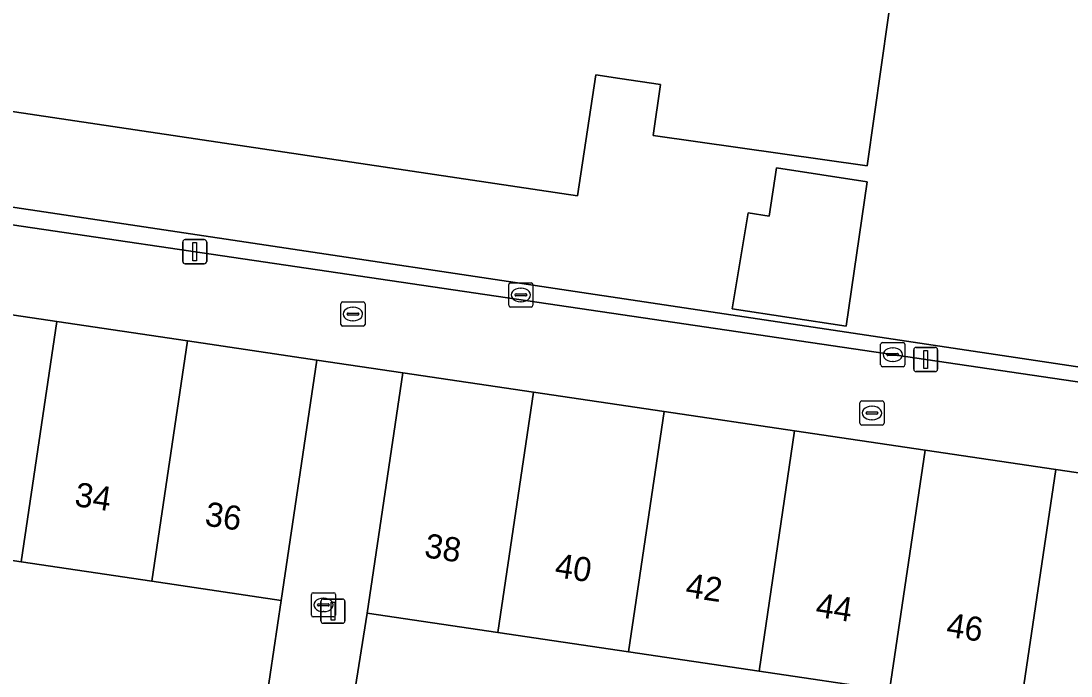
# Model space of a CAD drawing. Extents: x 164148 to 165261, y 382513 to 383432.
# Drawn here: x 164475.24 to 164518.66, y 383338.67 to 383365.77 of the extents above; entities that cross this region are included whole.
import ezdxf

# ---------------------------------------------------------------- set-up
doc = ezdxf.new("R2010")
doc.units = 0
for name, color, linetype in [('IMGEO_Brandkraan', 7, 'Continuous'), ('IMGEO_Erf', 7, 'Continuous'), ('IMGEO_Groenvoorziening', 7, 'Continuous'), ('IMGEO_Hek', 7, 'Continuous'), ('IMGEO_Kolk', 7, 'Continuous'), ('IMGEO_Lichtmast', 7, 'Continuous'), ('IMGEO_Pand', 7, 'Continuous'), ('IMGEO_Pand_nummerreeks', 7, 'Continuous'), ('IMGEO_Rioolput', 7, 'Continuous'), ('IMGEO_Voetpad_open', 7, 'Continuous')]:
    doc.layers.add(name, color=color, linetype=linetype)

msp = doc.modelspace()

# ---------------------------------------------------------------- linework, layer by layer
at = {"layer": 'IMGEO_Brandkraan'}
for p, q in [((164509.93, 383349.123), (164509.93, 383349.975)), ((164510.005, 383350.049), (164510.857, 383350.049)), ((164510.418, 383349.829), (164510.443, 383349.829)), ((164510.931, 383349.975), (164510.931, 383349.123)), ((164510.189, 383349.543), (164510.189, 383349.555)), ((164510.627, 383349.506), (164510.229, 383349.506)), ((164510.232, 383349.592), (164510.63, 383349.592)), ((164510.673, 383349.555), (164510.673, 383349.543)), ((164510.857, 383349.049), (164510.005, 383349.049)), ((164510.441, 383349.269), (164510.416, 383349.269))]:
    msp.add_line(p, q, dxfattribs=at)
for points in [[(164509.93, 383349.123), (164509.93, 383349.975)], [(164510.005, 383350.049), (164510.857, 383350.049)], [(164510.931, 383349.975), (164510.931, 383349.123)], [(164510.857, 383349.049), (164510.005, 383349.049)]]:
    msp.add_lwpolyline(points, dxfattribs=at)
for centre, radius, start, end in [((164510.007, 383349.973), 0.0765, 91.552, 178.448), ((164510.007, 383349.973), 0.0765, 91.552, 178.448), ((164510.855, 383349.973), 0.0765, 1.552, 88.448), ((164510.855, 383349.973), 0.0765, 1.552, 88.448), ((164510.229, 383349.552), 0.0403, 85.8775, 175.7526), ((164510.226, 383349.542), 0.0366, 178.938, 274.7102), ((164510.63, 383349.549), 0.043, 264.8664, 352.4533), ((164510.634, 383349.554), 0.0386, 1.7309, 96.639), ((164510.007, 383349.125), 0.0765, 181.552, 268.448), ((164510.007, 383349.125), 0.0765, 181.552, 268.448), ((164510.855, 383349.125), 0.0765, 271.552, 358.448), ((164510.855, 383349.125), 0.0765, 271.552, 358.448)]:
    msp.add_arc(centre, radius, start, end, dxfattribs=at)
for centre, major_axis, ratio, start_param, end_param in [((164510.417, 383349.549), (-0.387, 0.002), 0.722429, 4.712389, 7.853982), ((164510.442, 383349.549), (-0.39, 0.002), 0.717154, 1.570796, 4.712389)]:
    msp.add_ellipse(centre, major_axis=major_axis, ratio=ratio, start_param=start_param, end_param=end_param, dxfattribs=at)
at = {"layer": 'IMGEO_Erf'}
for points in [[(164496.172, 383394.152), (164495.205, 383395.312), (164485.846, 383406.541), (164475.669, 383398.705), (164457.962, 383391.157), (164451.983, 383388.33), (164443.993, 383384.279), (164439.097, 383382.204), (164431.513, 383378.99), (164421.044, 383374.785), (164425.292, 383365.326), (164446.405, 383362.194), (164456.026, 383360.895), (164526.656, 383350.3), (164530.567, 383353.579)], [(164506.481, 383359.697), (164510.237, 383359.121), (164509.366, 383353.137), (164504.653, 383353.864), (164505.307, 383357.838), (164506.183, 383357.694)], [(164480.652, 383342.588), (164475.251, 383343.388), (164469.85, 383344.188), (164464.449, 383344.988), (164459.047, 383345.788), (164453.646, 383346.588), (164448.245, 383347.387), (164442.844, 383348.187), (164437.443, 383348.987), (164432.042, 383349.787), (164430.539, 383340.579), (164484.639, 383332.608), (164486.005, 383341.796)], [(164527.364, 383335.671), (164521.963, 383336.471), (164516.562, 383337.27), (164511.161, 383338.07), (164505.76, 383338.87), (164500.359, 383339.67), (164494.958, 383340.47), (164489.556, 383341.27), (164488.094, 383332.078), (164531.533, 383325.667), (164532.785, 383334.868)]]:
    msp.add_lwpolyline(points, close=True, dxfattribs=at)
msp.add_lwpolyline([(164511.684, 383370.001), (164510.233, 383359.776), (164501.382, 383361.033), (164501.681, 383363.14), (164500, 383363.392), (164499.006, 383363.541), (164498.259, 383358.532), (164472.187, 383362.422), (164472.098, 383361.829), (164466.687, 383362.633), (164467.658, 383369.162)], dxfattribs=at)
at = {"layer": 'IMGEO_Groenvoorziening'}
msp.add_lwpolyline([(164433.986, 383363.368), (164526.587, 383349.71), (164526.656, 383350.3), (164456.026, 383360.895), (164446.405, 383362.194), (164425.292, 383365.326), (164425.46, 383364.655)], close=True, dxfattribs=at)
at = {"layer": 'IMGEO_Hek'}
msp.add_lwpolyline([(164526.656, 383350.3), (164456.026, 383360.895), (164446.405, 383362.194), (164425.292, 383365.326)], dxfattribs=at)
at = {"layer": 'IMGEO_Kolk'}
for p, q in [((164495.409, 383354.01), (164495.409, 383354.862)), ((164495.484, 383354.936), (164496.336, 383354.936)), ((164495.897, 383354.716), (164495.922, 383354.716)), ((164496.41, 383354.862), (164496.41, 383354.01)), ((164495.668, 383354.43), (164495.668, 383354.442)), ((164496.106, 383354.393), (164495.708, 383354.393)), ((164495.711, 383354.479), (164496.109, 383354.479)), ((164495.92, 383354.156), (164495.895, 383354.156)), ((164496.152, 383354.442), (164496.152, 383354.43)), ((164496.336, 383353.936), (164495.484, 383353.936)), ((164510.864, 383352.467), (164511.716, 383352.467)), ((164510.789, 383351.541), (164510.789, 383352.393)), ((164511.091, 383352.01), (164511.489, 383352.01)), ((164511.277, 383352.247), (164511.302, 383352.247)), ((164511.79, 383352.393), (164511.79, 383351.541)), ((164511.048, 383351.961), (164511.048, 383351.973)), ((164511.486, 383351.924), (164511.088, 383351.924)), ((164511.3, 383351.687), (164511.275, 383351.687)), ((164511.532, 383351.973), (164511.532, 383351.961)), ((164511.716, 383351.467), (164510.864, 383351.467)), ((164487.247, 383341.185), (164487.247, 383342.037)), ((164487.322, 383342.111), (164488.174, 383342.111)), ((164488.248, 383342.037), (164488.248, 383341.185)), ((164487.506, 383341.605), (164487.506, 383341.617)), ((164487.944, 383341.568), (164487.546, 383341.568)), ((164487.549, 383341.654), (164487.947, 383341.654)), ((164487.735, 383341.891), (164487.76, 383341.891)), ((164487.99, 383341.617), (164487.99, 383341.605)), ((164487.758, 383341.331), (164487.733, 383341.331)), ((164488.174, 383341.111), (164487.322, 383341.111))]:
    msp.add_line(p, q, dxfattribs=at)
for points in [[(164495.409, 383354.01), (164495.409, 383354.862)], [(164495.484, 383354.936), (164496.336, 383354.936)], [(164496.41, 383354.862), (164496.41, 383354.01)], [(164496.336, 383353.936), (164495.484, 383353.936)], [(164510.864, 383352.467), (164511.716, 383352.467)], [(164510.789, 383351.541), (164510.789, 383352.393)], [(164511.79, 383352.393), (164511.79, 383351.541)], [(164511.716, 383351.467), (164510.864, 383351.467)], [(164487.247, 383341.185), (164487.247, 383342.037)], [(164487.322, 383342.111), (164488.174, 383342.111)], [(164488.248, 383342.037), (164488.248, 383341.185)], [(164488.174, 383341.111), (164487.322, 383341.111)]]:
    msp.add_lwpolyline(points, dxfattribs=at)
for centre, radius, start, end in [((164495.486, 383354.86), 0.0765, 91.552, 178.448), ((164495.486, 383354.86), 0.0765, 91.552, 178.448), ((164496.334, 383354.86), 0.0765, 1.552, 88.448), ((164496.334, 383354.86), 0.0765, 1.552, 88.448), ((164495.708, 383354.439), 0.0403, 85.8775, 175.7526), ((164495.705, 383354.429), 0.0366, 178.938, 274.7102), ((164496.109, 383354.436), 0.043, 264.8664, 352.4533), ((164496.113, 383354.441), 0.0386, 1.7309, 96.639), ((164495.486, 383354.012), 0.0765, 181.552, 268.448), ((164495.486, 383354.012), 0.0765, 181.552, 268.448), ((164496.334, 383354.012), 0.0765, 271.552, 358.448), ((164496.334, 383354.012), 0.0765, 271.552, 358.448), ((164510.866, 383352.391), 0.0765, 91.552, 178.448), ((164510.866, 383352.391), 0.0765, 91.552, 178.448), ((164511.714, 383352.391), 0.0765, 1.552, 88.448), ((164511.714, 383352.391), 0.0765, 1.552, 88.448), ((164511.088, 383351.97), 0.0403, 85.8775, 175.7526), ((164511.493, 383351.972), 0.0386, 1.7309, 96.639), ((164511.085, 383351.96), 0.0366, 178.938, 274.7102), ((164511.489, 383351.967), 0.043, 264.8664, 352.4533), ((164510.866, 383351.543), 0.0765, 181.552, 268.448), ((164510.866, 383351.543), 0.0765, 181.552, 268.448), ((164511.714, 383351.543), 0.0765, 271.552, 358.448), ((164511.714, 383351.543), 0.0765, 271.552, 358.448), ((164487.324, 383342.035), 0.0765, 91.552, 178.448), ((164487.324, 383342.035), 0.0765, 91.552, 178.448), ((164488.172, 383342.035), 0.0765, 1.552, 88.448), ((164488.172, 383342.035), 0.0765, 1.552, 88.448), ((164487.546, 383341.614), 0.0403, 85.8775, 175.7526), ((164487.543, 383341.604), 0.0366, 178.938, 274.7102), ((164487.947, 383341.611), 0.043, 264.8664, 352.4533), ((164487.951, 383341.616), 0.0386, 1.7309, 96.639), ((164487.324, 383341.187), 0.0765, 181.552, 268.448), ((164487.324, 383341.187), 0.0765, 181.552, 268.448), ((164488.172, 383341.187), 0.0765, 271.552, 358.448), ((164488.172, 383341.187), 0.0765, 271.552, 358.448)]:
    msp.add_arc(centre, radius, start, end, dxfattribs=at)
for centre, major_axis, ratio, start_param, end_param in [((164495.896, 383354.436), (-0.387, 0.002), 0.722429, 4.712389, 7.853982), ((164495.921, 383354.436), (-0.39, 0.002), 0.717154, 1.570796, 4.712389), ((164511.276, 383351.967), (-0.387, 0.002), 0.722429, 4.712389, 7.853982), ((164511.301, 383351.967), (-0.39, 0.002), 0.717154, 1.570796, 4.712389), ((164487.734, 383341.611), (-0.387, 0.002), 0.722429, 4.712389, 7.853982), ((164487.759, 383341.611), (-0.39, 0.002), 0.717154, 1.570796, 4.712389)]:
    msp.add_ellipse(centre, major_axis=major_axis, ratio=ratio, start_param=start_param, end_param=end_param, dxfattribs=at)
at = {"layer": 'IMGEO_Lichtmast'}
for p, q in [((164481.928, 383355.824), (164481.928, 383356.624)), ((164481.928, 383356.624), (164481.928, 383355.824)), ((164482.028, 383356.724), (164482.818, 383356.724)), ((164482.818, 383356.724), (164482.028, 383356.724)), ((164482.918, 383356.624), (164482.918, 383355.824)), ((164482.918, 383355.824), (164482.918, 383356.624)), ((164482.818, 383355.724), (164482.028, 383355.724)), ((164482.028, 383355.724), (164482.818, 383355.724)), ((164512.155, 383351.366), (164512.155, 383352.166)), ((164512.155, 383352.166), (164512.155, 383351.366)), ((164512.255, 383352.266), (164513.045, 383352.266)), ((164513.045, 383352.266), (164512.255, 383352.266)), ((164513.145, 383352.166), (164513.145, 383351.366)), ((164513.145, 383351.366), (164513.145, 383352.166)), ((164513.045, 383351.266), (164512.255, 383351.266)), ((164512.255, 383351.266), (164513.045, 383351.266)), ((164487.643, 383340.949), (164487.643, 383341.749)), ((164487.643, 383341.749), (164487.643, 383340.949)), ((164487.743, 383341.849), (164488.533, 383341.849)), ((164488.533, 383341.849), (164487.743, 383341.849)), ((164488.633, 383341.749), (164488.633, 383340.949)), ((164488.633, 383340.949), (164488.633, 383341.749)), ((164488.533, 383340.849), (164487.743, 383340.849)), ((164487.743, 383340.849), (164488.533, 383340.849))]:
    msp.add_line(p, q, dxfattribs=at)
for points in [[(164482.348, 383356.599), (164482.498, 383356.599), (164482.498, 383355.849), (164482.348, 383355.849), (164482.348, 383356.599)], [(164512.575, 383352.141), (164512.725, 383352.141), (164512.725, 383351.391), (164512.575, 383351.391), (164512.575, 383352.141)], [(164488.063, 383341.724), (164488.213, 383341.724), (164488.213, 383340.974), (164488.063, 383340.974), (164488.063, 383341.724)]]:
    msp.add_lwpolyline(points, dxfattribs=at)
for centre, start, end in [((164482.028, 383356.624), 90, 180), ((164482.028, 383356.624), 90, 180), ((164482.818, 383356.624), 0, 90), ((164482.818, 383356.624), 360, 90), ((164482.028, 383355.824), 180, 270), ((164482.028, 383355.824), 180, 270), ((164482.818, 383355.824), 270, 0), ((164482.818, 383355.824), 270, 0), ((164512.255, 383352.166), 90, 180), ((164512.255, 383352.166), 90, 180), ((164513.045, 383352.166), 0, 90), ((164513.045, 383352.166), 360, 90), ((164512.255, 383351.366), 180, 270), ((164512.255, 383351.366), 180, 270), ((164513.045, 383351.366), 270, 0), ((164513.045, 383351.366), 270, 0), ((164487.743, 383341.749), 90, 180), ((164487.743, 383341.749), 90, 180), ((164488.533, 383341.749), 0, 90), ((164488.533, 383341.749), 360, 90), ((164487.743, 383340.949), 180, 270), ((164487.743, 383340.949), 180, 270), ((164488.533, 383340.949), 270, 0), ((164488.533, 383340.949), 270, 0)]:
    msp.add_arc(centre, 0.1, start, end, dxfattribs=at)
at = {"layer": 'IMGEO_Pand'}
msp.add_lwpolyline([(164467.658, 383369.162), (164466.687, 383362.633), (164472.098, 383361.829), (164472.187, 383362.422), (164498.259, 383358.532), (164499.006, 383363.541), (164500, 383363.392), (164501.681, 383363.14), (164501.382, 383361.033), (164510.233, 383359.776), (164511.684, 383370.001)], dxfattribs=at)
for points in [[(164504.653, 383353.864), (164509.366, 383353.137), (164510.237, 383359.121), (164506.481, 383359.697), (164506.183, 383357.694), (164505.307, 383357.838)], [(164475.251, 383343.388), (164476.723, 383353.33), (164471.322, 383354.13), (164469.85, 383344.188)], [(164475.251, 383343.388), (164480.652, 383342.588), (164482.124, 383352.53), (164476.723, 383353.33)], [(164480.652, 383342.588), (164486.005, 383341.796), (164487.477, 383351.737), (164482.124, 383352.53)], [(164496.43, 383350.411), (164491.029, 383351.211), (164489.556, 383341.27), (164494.958, 383340.47)], [(164496.43, 383350.411), (164494.958, 383340.47), (164500.359, 383339.67), (164501.831, 383349.612)], [(164507.232, 383348.812), (164501.831, 383349.612), (164500.359, 383339.67), (164505.76, 383338.87)], [(164512.633, 383348.012), (164507.232, 383348.812), (164505.76, 383338.87), (164511.161, 383338.07)], [(164512.633, 383348.012), (164511.161, 383338.07), (164516.562, 383337.27), (164518.034, 383347.212)], [(164521.963, 383336.471), (164523.435, 383346.412), (164518.034, 383347.212), (164516.562, 383337.27)]]:
    msp.add_lwpolyline(points, close=True, dxfattribs=at)
at = {"layer": 'IMGEO_Rioolput'}
for p, q in [((164488.466, 383353.218), (164488.466, 383354.07)), ((164488.541, 383354.144), (164489.393, 383354.144)), ((164488.954, 383353.924), (164488.979, 383353.924)), ((164489.467, 383354.07), (164489.467, 383353.218)), ((164488.725, 383353.638), (164488.725, 383353.65)), ((164489.163, 383353.601), (164488.765, 383353.601)), ((164488.768, 383353.687), (164489.166, 383353.687)), ((164488.977, 383353.364), (164488.952, 383353.364)), ((164489.209, 383353.65), (164489.209, 383353.638)), ((164489.393, 383353.144), (164488.541, 383353.144))]:
    msp.add_line(p, q, dxfattribs=at)
for points in [[(164488.466, 383353.218), (164488.466, 383354.07)], [(164488.541, 383354.144), (164489.393, 383354.144)], [(164489.467, 383354.07), (164489.467, 383353.218)], [(164489.393, 383353.144), (164488.541, 383353.144)]]:
    msp.add_lwpolyline(points, dxfattribs=at)
for centre, radius, start, end in [((164488.543, 383354.068), 0.0765, 91.552, 178.448), ((164488.543, 383354.068), 0.0765, 91.552, 178.448), ((164489.391, 383354.068), 0.0765, 1.552, 88.448), ((164489.391, 383354.068), 0.0765, 1.552, 88.448), ((164488.765, 383353.647), 0.0403, 85.8775, 175.7526), ((164488.762, 383353.637), 0.0366, 178.938, 274.7102), ((164489.166, 383353.644), 0.043, 264.8664, 352.4533), ((164489.17, 383353.649), 0.0386, 1.7309, 96.639), ((164488.543, 383353.22), 0.0765, 181.552, 268.448), ((164488.543, 383353.22), 0.0765, 181.552, 268.448), ((164489.391, 383353.22), 0.0765, 271.552, 358.448), ((164489.391, 383353.22), 0.0765, 271.552, 358.448)]:
    msp.add_arc(centre, radius, start, end, dxfattribs=at)
for centre, major_axis, ratio, start_param, end_param in [((164488.953, 383353.644), (-0.387, 0.002), 0.722429, 4.712389, 7.853982), ((164488.978, 383353.644), (-0.39, 0.002), 0.717154, 1.570796, 4.712389)]:
    msp.add_ellipse(centre, major_axis=major_axis, ratio=ratio, start_param=start_param, end_param=end_param, dxfattribs=at)
at = {"layer": 'IMGEO_Voetpad_open'}
for points in [[(164471.322, 383354.13), (164476.723, 383353.33), (164482.124, 383352.53), (164487.477, 383351.737), (164491.029, 383351.211), (164496.43, 383350.411), (164501.831, 383349.612), (164507.232, 383348.812), (164512.633, 383348.012), (164518.034, 383347.212), (164523.435, 383346.412), (164528.836, 383345.612), (164534.257, 383344.81), (164536.279, 383342.366), (164540.588, 383341.709), (164541.451, 383347.518), (164536.236, 383348.287), (164526.587, 383349.71), (164433.986, 383363.368)], [(164536.279, 383342.366), (164534.257, 383344.81), (164533.932, 383342.614), (164532.785, 383334.868), (164531.533, 383325.667), (164488.094, 383332.078), (164489.556, 383341.27), (164491.029, 383351.211), (164487.477, 383351.737), (164486.005, 383341.796), (164484.639, 383332.608), (164430.539, 383340.579), (164432.042, 383349.787), (164433.514, 383359.729), (164429.933, 383360.28), (164428.467, 383350.338), (164427.117, 383341.092), (164383.799, 383347.483), (164383.752, 383345.842), (164388.671, 383345.12), (164390.731, 383344.808), (164424.372, 383339.822)]]:
    msp.add_lwpolyline(points, dxfattribs=at)

# ---------------------------------------------------------------- texts
at = {"layer": 'IMGEO_Pand_nummerreeks'}
for s, rotation, p in [('34', 351.4801, (164477.418, 383345.707)), ('36', 351.4801, (164482.806, 383344.899)), ('38', 351.3483, (164491.883, 383343.589)), ('40', 351.3483, (164497.278, 383342.768)), ('42', 351.3483, (164502.684, 383341.946)), ('44', 351.3483, (164508.061, 383341.128)), ('46', 351.3483, (164513.465, 383340.306))]:
    msp.add_text(s, height=1, rotation=rotation, dxfattribs=at).set_placement(p)

doc.saveas('drawing.dxf')
